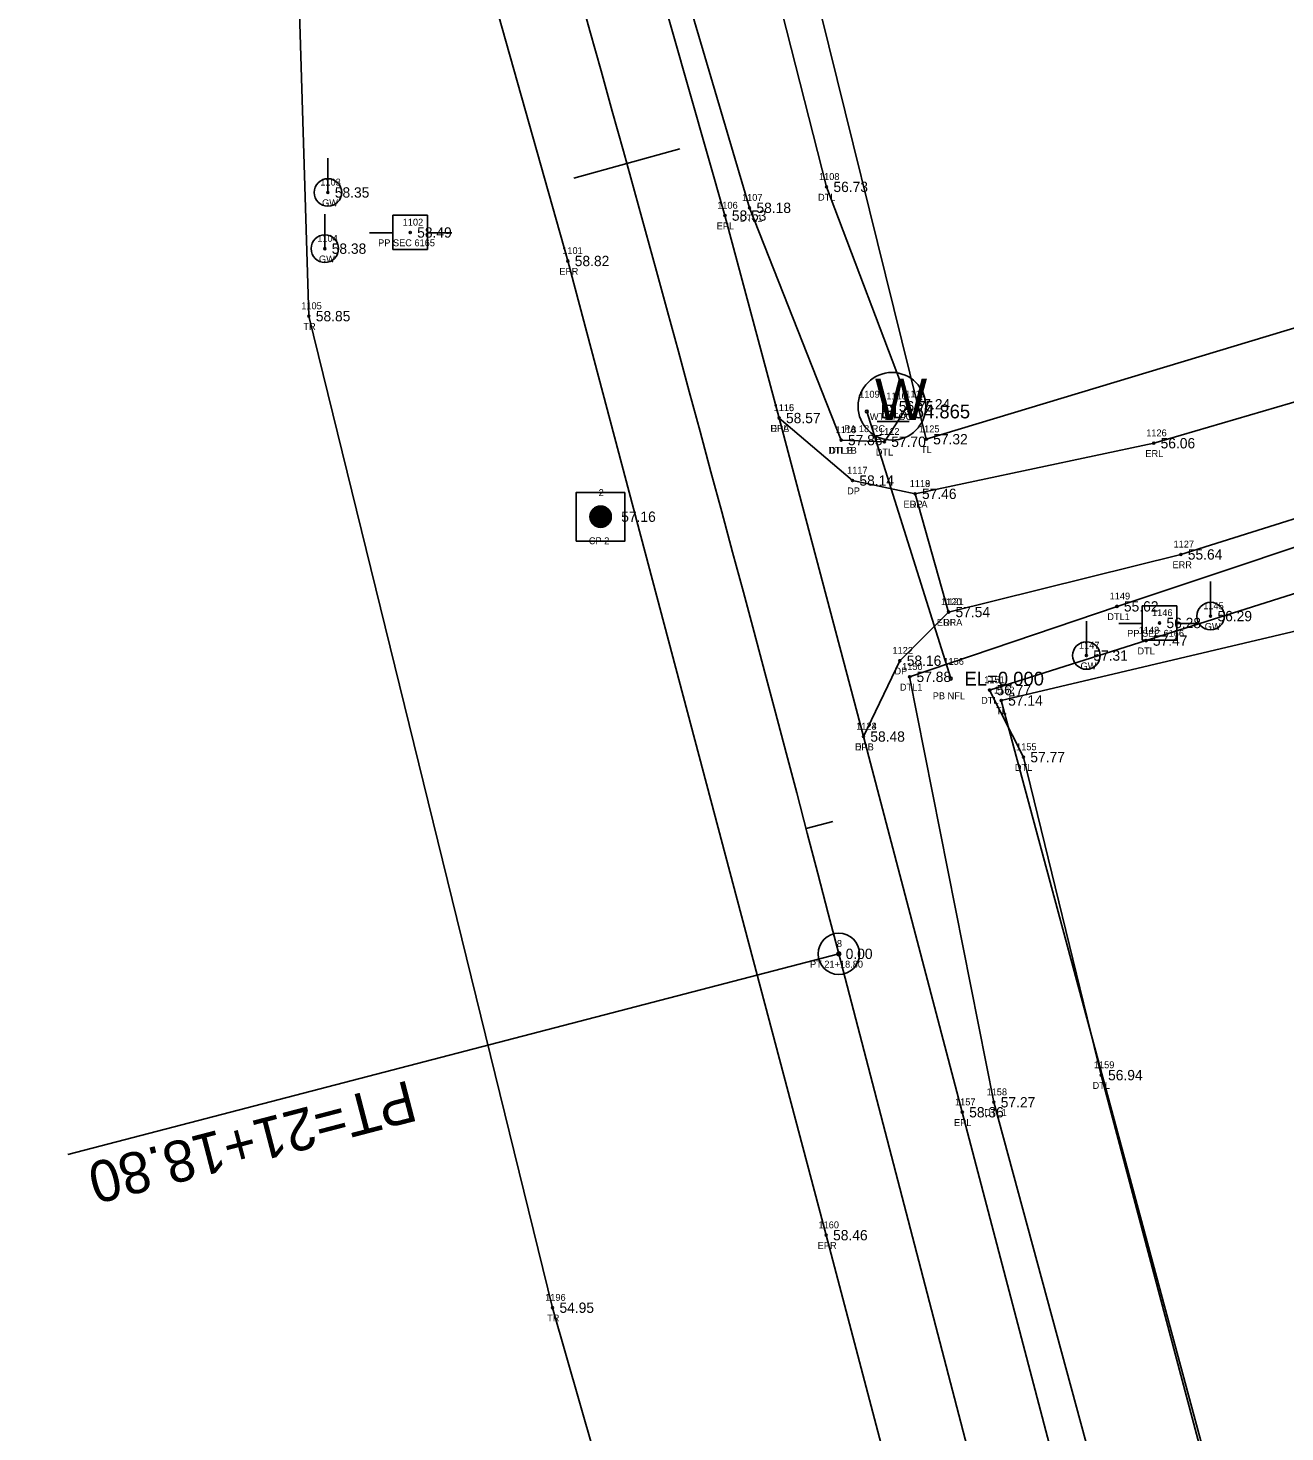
# Model space of a CAD drawing. Extents: x 2396531 to 2397633, y 770203 to 772837.
# Drawn here: x 2396869.2 to 2397051.8, y 771574.1 to 771777.9 of the extents above; entities that cross this region are included whole.
import ezdxf

# ---------------------------------------------------------------- set-up
doc = ezdxf.new("R2010")
doc.units = 0
for name, color, linetype in [('RD_EX_DR_Pipe', 7, 'Continuous'), ('RD_EX_DR_Pipe_txCode', 7, 'Continuous'), ('RD_EX_Driveway', 7, 'Continuous'), ('RD_EX_Driveway_txCode', 7, 'Continuous'), ('RD_EX_H2O', 7, 'Continuous'), ('RD_EX_H2O_txCode', 7, 'Continuous'), ('RD_EX_Road', 7, 'Continuous'), ('RD_EX_Road_txCode', 7, 'Continuous'), ('RD_EX_TX_Driveway_ELEV', 7, 'Continuous'), ('RD_EX_TX_H2O_ELEV', 7, 'Continuous'), ('RD_EX_TX_Road_ELEV', 7, 'Continuous'), ('RD_EX_TX_UT_ELEV', 7, 'Continuous'), ('RD_EX_TX_VEG_ELEV', 7, 'Continuous'), ('RD_EX_UT', 7, 'Continuous'), ('RD_EX_UT_txCode', 7, 'Continuous'), ('RD_EX_VEG', 7, 'Continuous'), ('RD_EX_VEG_txCode', 7, 'Continuous'), ('RD_HC_Cl', 7, 'Continuous'), ('RD_HC_Data', 7, 'Continuous'), ('RD_HC_Data_Tic', 7, 'Continuous'), ('RD_HC_Survey', 7, 'Continuous'), ('RD_HC_Survey_ELEV', 7, 'Continuous'), ('RD_HC_Survey_txCode', 7, 'Continuous'), ('RD_HC_txCode', 7, 'Continuous'), ('RD_SMD_Locator', 7, 'Continuous'), ('RD_TX_Pipe_ElevEX', 7, 'Continuous')]:
    doc.layers.add(name, color=color, linetype=linetype)

msp = doc.modelspace()

# ---------------------------------------------------------------- linework, layer by layer
at = {"layer": 'RD_EX_DR_Pipe'}
msp.add_line((2396991.06, 771722.24), (2397003.27, 771683.45), dxfattribs=at)
at = {"layer": 'RD_EX_Driveway'}
msp.add_lwpolyline([(2396978.33, 771721.29), (2396988.99, 771712.21), (2396998.08, 771710.28), (2397002.95, 771693.12), (2396995.87, 771686.05), (2396990.58, 771675.04)], dxfattribs=at)
at = {"layer": 'RD_EX_H2O'}
for points in [[(2396946.35, 771904.67), (2396938.36, 771904.07), (2396931.6, 771898.52), (2396953.06, 771822.86), (2396974.04, 771751.81), (2396987.33, 771718.09)], [(2396946.35, 771904.67), (2396967.2, 771825.55), (2396985.22, 771754.85), (2396997.16, 771723.28), (2396993.62, 771717.84), (2396987.33, 771718.09)], [(2397132.06, 771727.73), (2397069.65, 771707.99), (2397027.41, 771693.94), (2396997.29, 771683.71), (2397009.52, 771621.94), (2397039.8, 771510.33), (2397059.22, 771428.3), (2397068.26, 771415.82), (2397065.8, 771409.74)], [(2397133.83, 771721.66), (2397071.25, 771701.52), (2397031.62, 771688.97), (2397008.91, 771681.79), (2397013.82, 771672.05), (2397025.11, 771625.88), (2397054.64, 771514.68), (2397075.97, 771429.94), (2397072.44, 771413.81)]]:
    msp.add_lwpolyline(points, dxfattribs=at)
at = {"layer": 'RD_EX_Road'}
for points in [[(2396680.92, 772617.84), (2396715.6, 772525.73), (2396750.68, 772430.62), (2396786.3, 772332.21), (2396811.38, 772263.31), (2396839.69, 772181.74), (2396863.75, 772109.83), (2396883.63, 772046.56), (2396889.54, 772027.11), (2396896.25, 772004.37), (2396904.34, 771978.33), (2396908.24, 771964.89), (2396921.74, 771919.68), (2396927.03, 771902.11), (2396950.2, 771821.74), (2396970.47, 771750.68), (2396978.33, 771721.29), (2396990.58, 771675.04), (2397004.94, 771620.49), (2397034.26, 771508.8), (2397061.11, 771410.49), (2397060.64, 771407.04), (2397062.07, 771407.67)], [(2396658.78, 772611.07), (2396693.37, 772516.9), (2396729.65, 772418.78), (2396760.7, 772333.11), (2396788.58, 772254.87), (2396814.65, 772181.57), (2396841.1, 772100.86), (2396861.19, 772037.76), (2396886.09, 771955.71), (2396907.15, 771884.49), (2396928.56, 771811.72), (2396947.65, 771744.09), (2396985.17, 771602.64), (2397011.11, 771504.04), (2397037.95, 771404.25), (2397039, 771401.22)], [(2396998.08, 771710.28), (2397032.74, 771717.63), (2397062.52, 771726.35), (2397126.64, 771745.15)], [(2397002.95, 771693.12), (2397036.69, 771701.48), (2397068.39, 771711.44), (2397131.44, 771730.05)]]:
    msp.add_lwpolyline(points, dxfattribs=at)
at = {"layer": 'RD_EX_UT'}
for p, q in [((2396912.8, 771754.04), (2396912.8, 771759.04)), ((2396912.35, 771745.88), (2396912.35, 771750.88)), ((2396927.25, 771750.74), (2396922.25, 771750.74)), ((2396922.25, 771750.74), (2396922.25, 771745.74)), ((2396927.25, 771745.74), (2396927.25, 771750.74)), ((2396918.82, 771748.18), (2396922.29, 771748.18)), ((2396927.18, 771748.18), (2396930.82, 771748.18)), ((2396922.25, 771745.74), (2396927.25, 771745.74)), ((2396992.59, 771720.79), (2396997.22, 771720.79)), ((2397041, 771692.53), (2397041, 771697.53)), ((2397036.08, 771694.04), (2397031.08, 771694.04)), ((2397031.08, 771694.04), (2397031.08, 771689.04)), ((2397036.08, 771689.04), (2397036.08, 771694.04)), ((2397022.96, 771686.8), (2397022.96, 771691.8)), ((2397027.65, 771691.47), (2397031.12, 771691.47)), ((2397036.01, 771691.47), (2397039.65, 771691.47)), ((2397031.08, 771689.04), (2397036.08, 771689.04))]:
    msp.add_line(p, q, dxfattribs=at)
for centre, radius in [((2396912.8, 771754.04), 2), ((2396912.35, 771745.88), 2), ((2396994.72, 771722.99), 4.91), ((2397041, 771692.53), 2), ((2397022.96, 771686.8), 2)]:
    msp.add_circle(centre, radius, dxfattribs=at)
at = {"layer": 'RD_EX_VEG'}
for points in [[(2396666.35, 772324.52), (2396746.5, 772348.13), (2396878.43, 771953.6), (2396907.83, 771806.94), (2396910.04, 771736.08), (2396945.43, 771592.11), (2397049.51, 771229.15), (2396980.16, 771221.67)], [(2396927.91, 772008.32), (2396999.71, 771718.21), (2397059.32, 771736.23), (2397119.67, 771755.84)], [(2397137.17, 771710.16), (2397010.6, 771680.28), (2397078.29, 771429.37), (2397127.02, 771232.69), (2397127.02, 771232.69), (2397166.52, 771123.83), (2397178.02, 771098.29), (2397254.06, 771102.5)]]:
    msp.add_lwpolyline(points, dxfattribs=at)
at = {"layer": 'RD_HC_Cl'}
msp.add_line((2396987, 771643.49), (2397064.7, 771345.02), dxfattribs=at)
msp.add_arc((2389304.02, 769643.48), 7939.03, 14.59125, 20.164785, dxfattribs=at)
at = {"layer": 'RD_HC_Data'}
msp.add_line((2396987, 771643.49), (2396875.02, 771614.34), dxfattribs=at)
for radius in [3, 0.282]:
    msp.add_circle((2396987, 771643.49), radius, dxfattribs=at)
at = {"layer": 'RD_HC_Data_Tic'}
for p, q in [((2396956.22, 771758.23), (2396963.93, 771760.36)), ((2396956.22, 771758.23), (2396948.51, 771756.1)), ((2396982.25, 771661.68), (2396986.12, 771662.7))]:
    msp.add_line(p, q, dxfattribs=at)
at = {"layer": 'RD_HC_Survey'}
for p, q in [((2396950.94, 771706.43), (2396950.94, 771707.49)), ((2396950.99, 771706.31), (2396950.99, 771707.61)), ((2396951.04, 771706.21), (2396951.04, 771707.71)), ((2396951.09, 771706.12), (2396951.09, 771707.79)), ((2396951.14, 771706.05), (2396951.14, 771707.87)), ((2396951.19, 771705.98), (2396951.19, 771707.93)), ((2396951.24, 771705.93), (2396951.24, 771707.99)), ((2396951.29, 771705.87), (2396951.29, 771708.05)), ((2396951.34, 771705.82), (2396951.34, 771708.09)), ((2396951.39, 771705.78), (2396951.39, 771708.14)), ((2396951.44, 771705.74), (2396951.44, 771708.18)), ((2396951.49, 771705.7), (2396951.49, 771708.22)), ((2396951.54, 771705.66), (2396951.54, 771708.25)), ((2396951.59, 771705.63), (2396951.59, 771708.28)), ((2396951.64, 771705.6), (2396951.64, 771708.31)), ((2396951.69, 771705.58), (2396951.69, 771708.34)), ((2396951.74, 771705.55), (2396951.74, 771708.37)), ((2396951.79, 771705.53), (2396951.79, 771708.39)), ((2396951.84, 771705.51), (2396951.84, 771708.41)), ((2396951.89, 771705.49), (2396951.89, 771708.43)), ((2396951.94, 771705.47), (2396951.94, 771708.44)), ((2396951.99, 771705.46), (2396951.99, 771708.46)), ((2396952.04, 771705.45), (2396952.04, 771708.47)), ((2396952.09, 771705.44), (2396952.09, 771708.48)), ((2396952.14, 771705.43), (2396952.14, 771708.49)), ((2396952.19, 771705.42), (2396952.19, 771708.5)), ((2396952.24, 771705.41), (2396952.24, 771708.5)), ((2396952.29, 771705.41), (2396952.29, 771708.51)), ((2396952.34, 771705.41), (2396952.34, 771708.51)), ((2396952.39, 771705.4), (2396952.39, 771708.51)), ((2396952.44, 771705.4), (2396952.44, 771708.51)), ((2396952.49, 771705.41), (2396952.49, 771708.51)), ((2396952.54, 771705.41), (2396952.54, 771708.51)), ((2396952.59, 771705.42), (2396952.59, 771708.5)), ((2396952.64, 771705.42), (2396952.64, 771708.49)), ((2396952.69, 771705.43), (2396952.69, 771708.49)), ((2396952.74, 771705.44), (2396952.74, 771708.48)), ((2396952.79, 771705.45), (2396952.79, 771708.46)), ((2396952.84, 771705.47), (2396952.84, 771708.45)), ((2396952.89, 771705.48), (2396952.89, 771708.43)), ((2396952.94, 771705.5), (2396952.94, 771708.42)), ((2396952.99, 771705.52), (2396952.99, 771708.4)), ((2396953.04, 771705.54), (2396953.04, 771708.38)), ((2396953.09, 771705.56), (2396953.09, 771708.35)), ((2396953.14, 771705.59), (2396953.14, 771708.33)), ((2396953.19, 771705.62), (2396953.19, 771708.3)), ((2396953.24, 771705.65), (2396953.24, 771708.27)), ((2396953.29, 771705.68), (2396953.29, 771708.23)), ((2396953.34, 771705.72), (2396953.34, 771708.2)), ((2396953.39, 771705.76), (2396953.39, 771708.16)), ((2396953.44, 771705.8), (2396953.44, 771708.12)), ((2396953.49, 771705.85), (2396953.49, 771708.07)), ((2396953.54, 771705.9), (2396953.54, 771708.02)), ((2396953.59, 771705.96), (2396953.59, 771707.96)), ((2396953.64, 771706.02), (2396953.64, 771707.9)), ((2396953.69, 771706.09), (2396953.69, 771707.83)), ((2396953.74, 771706.17), (2396953.74, 771707.75)), ((2396953.79, 771706.26), (2396953.79, 771707.66)), ((2396953.84, 771706.37), (2396953.84, 771707.55)), ((2396950.89, 771706.6), (2396950.89, 771707.32)), ((2396953.89, 771706.51), (2396953.89, 771707.41)), ((2396953.94, 771706.73), (2396953.94, 771707.18))]:
    msp.add_line(p, q, dxfattribs=at)
msp.add_lwpolyline([(2396955.93, 771710.49), (2396948.86, 771710.49), (2396948.86, 771703.42), (2396955.93, 771703.42)], close=True, dxfattribs=at)
msp.add_circle((2396952.4, 771706.96), 1.55, dxfattribs=at)
at = {"layer": 'RD_SMD_Locator'}
for centre, radius in [((2396985.22, 771754.85), 0.15), ((2396912.8, 771754.04), 0.15), ((2396970.47, 771750.68), 0.15), ((2396974.04, 771751.81), 0.15), ((2396924.76, 771748.23), 0.15), ((2396912.35, 771745.88), 0.15), ((2396947.65, 771744.09), 0.15), ((2396910.04, 771736.08), 0.15), ((2396991.06, 771722.24), 0.2), ((2396994.72, 771722.99), 0.15), ((2396997.16, 771723.28), 0.15), ((2396978.33, 771721.29), 0.15), ((2396978.33, 771721.29), 0.15), ((2396987.33, 771718.09), 0.15), ((2396987.33, 771718.09), 0.15), ((2396993.62, 771717.84), 0.15), ((2396999.71, 771718.21), 0.15), ((2397032.74, 771717.63), 0.15), ((2396988.99, 771712.21), 0.15), ((2396998.08, 771710.28), 0.15), ((2396998.08, 771710.28), 0.15), ((2396952.4, 771706.96), 0.15), ((2397036.69, 771701.48), 0.15), ((2397002.95, 771693.12), 0.15), ((2397002.95, 771693.12), 0.15), ((2397027.41, 771693.94), 0.15), ((2397033.59, 771691.53), 0.15), ((2397041, 771692.53), 0.15), ((2397031.62, 771688.97), 0.15), ((2396995.87, 771686.05), 0.15), ((2397022.96, 771686.8), 0.15), ((2396997.29, 771683.71), 0.15), ((2397003.27, 771683.45), 0.2), ((2397008.91, 771681.79), 0.15), ((2397010.6, 771680.28), 0.15), ((2396990.58, 771675.04), 0.15), ((2396990.58, 771675.04), 0.15), ((2397013.82, 771672.05), 0.15), ((2396987, 771643.49), 0.15), ((2397025.11, 771625.88), 0.15), ((2397009.52, 771621.94), 0.15), ((2397004.94, 771620.49), 0.15), ((2396985.17, 771602.64), 0.15), ((2396945.43, 771592.11), 0.15)]:
    msp.add_circle(centre, radius, dxfattribs=at)

# ---------------------------------------------------------------- texts
at = {"layer": 'RD_EX_DR_Pipe_txCode'}
for s, p in [('1109', (2396989.96, 771724.24)), ('PA 18 RC', (2396987.77, 771719.24)), ('1156', (2397002.19, 771685.45)), ('PB NFL', (2397000.65, 771680.45))]:
    msp.add_text(s, height=1, dxfattribs=at).set_placement(p)
at = {"layer": 'RD_EX_Driveway_txCode'}
for s, p in [('1116', (2396977.53, 771722.29)), ('DPA', (2396977.06, 771719.29)), ('1117', (2396988.21, 771713.21)), ('1118', (2396997.3, 771711.28)), ('DP', (2396988.21, 771710.21)), ('DP', (2396997.3, 771708.28)), ('1120', (2397001.85, 771694.12)), ('DP', (2397002.17, 771691.12)), ('1122', (2396994.8, 771687.05)), ('DP', (2396995.09, 771684.05)), ('1123', (2396989.52, 771676.04)), ('DPB', (2396989.33, 771673.04))]:
    msp.add_text(s, height=1, dxfattribs=at).set_placement(p)
at = {"layer": 'RD_EX_H2O_txCode'}
for s, p in [('1108', (2396984.12, 771755.85)), ('1107', (2396972.94, 771752.81)), ('DTL', (2396983.98, 771752.85)), ('DTL1', (2396972.63, 771749.81)), ('1111', (2396996.66, 771724.28)), ('DTL', (2396995.91, 771721.28)), ('1113', (2396986.55, 771719.09)), ('1114', (2396986.55, 771719.09)), ('1112', (2396992.84, 771718.84)), ('DTL1B', (2396985.45, 771716.09)), ('DTLB', (2396985.61, 771716.09)), ('DTL', (2396992.37, 771715.84)), ('1149', (2397026.34, 771694.94)), ('DTL1', (2397026, 771691.94)), ('1148', (2397030.56, 771689.97)), ('DTL', (2397030.38, 771686.97)), ('1150', (2396996.19, 771684.71)), ('1151', (2397008.13, 771682.79)), ('DTL1', (2396995.88, 771681.71)), ('DTL', (2397007.67, 771679.79)), ('1155', (2397012.75, 771673.05)), ('DTL', (2397012.57, 771670.05)), ('1159', (2397024.05, 771626.88)), ('1158', (2397008.46, 771622.94)), ('DTL', (2397023.86, 771623.88)), ('DTL1', (2397008.11, 771619.94))]:
    msp.add_text(s, height=1, dxfattribs=at).set_placement(p)
at = {"layer": 'RD_EX_Road_txCode'}
for s, p in [('1106', (2396969.34, 771751.68)), ('EPL', (2396969.26, 771748.68)), ('1101', (2396946.83, 771745.09)), ('EPR', (2396946.42, 771742.09)), ('1115', (2396977.55, 771722.29)), ('EPL', (2396977.13, 771719.29)), ('1126', (2397031.65, 771718.63)), ('ERL', (2397031.53, 771715.63)), ('1119', (2396997.3, 771711.28)), ('ERLA', (2396996.39, 771708.28)), ('1127', (2397035.62, 771702.48)), ('ERR', (2397035.46, 771699.48)), ('1121', (2397002.17, 771694.12)), ('ERRA', (2397001.23, 771691.12)), ('1124', (2396989.52, 771676.04)), ('EPL', (2396989.38, 771673.04)), ('1157', (2397003.88, 771621.49)), ('EPL', (2397003.74, 771618.49)), ('1160', (2396984.05, 771603.64)), ('EPR', (2396983.94, 771600.64))]:
    msp.add_text(s, height=1, dxfattribs=at).set_placement(p)
at = {"layer": 'RD_EX_TX_Driveway_ELEV'}
for s, p in [('58.57', (2396979.33, 771720.54)), ('58.14', (2396989.99, 771711.46)), ('57.46', (2396999.08, 771709.53)), ('57.54', (2397003.95, 771692.37)), ('58.16', (2396996.87, 771685.3)), ('58.48', (2396991.58, 771674.29))]:
    msp.add_text(s, height=1.5, dxfattribs=at).set_placement(p)
at = {"layer": 'RD_EX_TX_H2O_ELEV'}
for s, p in [('56.73', (2396986.22, 771754.1)), ('58.18', (2396975.04, 771751.06)), ('57.24', (2396998.16, 771722.53)), ('57.85', (2396988.33, 771717.34)), ('57.85', (2396988.33, 771717.34)), ('57.70', (2396994.62, 771717.09)), ('55.62', (2397028.41, 771693.19)), ('57.47', (2397032.62, 771688.22)), ('57.88', (2396998.29, 771682.96)), ('56.77', (2397009.91, 771681.04)), ('57.77', (2397014.82, 771671.3)), ('56.94', (2397026.11, 771625.13)), ('57.27', (2397010.52, 771621.19))]:
    msp.add_text(s, height=1.5, dxfattribs=at).set_placement(p)
at = {"layer": 'RD_EX_TX_Road_ELEV'}
for s, p in [('58.53', (2396971.47, 771749.93)), ('58.82', (2396948.65, 771743.34)), ('58.57', (2396979.33, 771720.54)), ('56.06', (2397033.74, 771716.88)), ('57.46', (2396999.08, 771709.53)), ('55.64', (2397037.69, 771700.73)), ('57.54', (2397003.95, 771692.37)), ('58.48', (2396991.58, 771674.29)), ('58.36', (2397005.94, 771619.74)), ('58.46', (2396986.17, 771601.89))]:
    msp.add_text(s, height=1.5, dxfattribs=at).set_placement(p)
at = {"layer": 'RD_EX_TX_UT_ELEV'}
for s, p in [('58.35', (2396913.8, 771753.29)), ('58.38', (2396913.35, 771745.13)), ('56.75', (2396995.72, 771722.24)), ('56.29', (2397042, 771691.78)), ('57.31', (2397023.96, 771686.05))]:
    msp.add_text(s, height=1.5, dxfattribs=at).set_placement(p)
at = {"layer": 'RD_EX_TX_VEG_ELEV'}
for s, p in [('58.85', (2396911.04, 771735.33)), ('57.32', (2397000.71, 771717.46)), ('57.14', (2397011.6, 771679.53)), ('54.95', (2396946.43, 771591.36))]:
    msp.add_text(s, height=1.5, dxfattribs=at).set_placement(p)
at = {"layer": 'RD_EX_UT'}
msp.add_text('W', height=6, dxfattribs=at).set_placement((2396992.26, 771720.99))
at = {"layer": 'RD_EX_UT_txCode'}
for s, p in [('1103', (2396911.69, 771755.04)), ('GW', (2396911.95, 771752.04)), ('1102', (2396923.66, 771749.23)), ('1104', (2396911.25, 771746.88)), ('PP SEC 6165', (2396920.09, 771746.23)), ('GW', (2396911.5, 771743.88)), ('1110', (2396993.9, 771723.99)), ('WTS FOC', (2396991.51, 771720.99)), ('1146', (2397032.5, 771692.53)), ('1145', (2397039.93, 771693.53)), ('GW', (2397040.15, 771690.53)), ('PP SEC 6166', (2397028.89, 771689.53)), ('1147', (2397021.89, 771687.8)), ('GW', (2397022.11, 771684.8))]:
    msp.add_text(s, height=1, dxfattribs=at).set_placement(p)
at = {"layer": 'RD_EX_VEG_txCode'}
for s, p in [('1105', (2396908.93, 771737.08)), ('TR', (2396909.24, 771734.08)), ('1125', (2396998.65, 771719.21)), ('TL', (2396998.94, 771716.21)), ('1152', (2397009.54, 771681.28)), ('TL', (2397009.83, 771678.28)), ('1196', (2396944.35, 771593.11)), ('TR', (2396944.64, 771590.11))]:
    msp.add_text(s, height=1, dxfattribs=at).set_placement(p)
at = {"layer": 'RD_HC_Data'}
msp.add_text('PT=21+18.80', height=6, rotation=194.5913, dxfattribs=at).set_placement((2396924.6, 771625.18))
at = {"layer": 'RD_HC_Survey_ELEV'}
for s, p in [('58.49', (2396925.76, 771747.48)), ('57.16', (2396955.4, 771706.21)), ('56.28', (2397034.59, 771690.78)), ('0.00', (2396988, 771642.74))]:
    msp.add_text(s, height=1.5, dxfattribs=at).set_placement(p)
at = {"layer": 'RD_HC_Survey_txCode'}
for s, p in [('2', (2396952.12, 771709.96)), ('CP 2', (2396950.7, 771702.96))]:
    msp.add_text(s, height=1, dxfattribs=at).set_placement(p)
at = {"layer": 'RD_HC_txCode'}
for s, p in [('8', (2396986.72, 771644.49)), ('PT 21+18.80', (2396982.82, 771641.49))]:
    msp.add_text(s, height=1, dxfattribs=at).set_placement(p)
at = {"layer": 'RD_TX_Pipe_ElevEX'}
for s, p in [('EL=54.865', (2396993.06, 771721.24)), ('EL=0.000', (2397005.27, 771682.45))]:
    msp.add_text(s, height=2, dxfattribs=at).set_placement(p)

doc.saveas('drawing.dxf')
